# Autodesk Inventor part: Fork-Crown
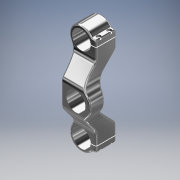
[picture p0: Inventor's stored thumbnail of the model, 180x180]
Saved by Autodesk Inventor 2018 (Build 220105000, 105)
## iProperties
Shininess: 64.0
Length Units: 11272
Angle Units: 11279
Time Units: 11290
Mass Units: 11286
Length Display Precision: 3
Angle Display Precision: 2
Compacted: True
Created: 2001-11
Part Number: Fork-Crown
Document SubType Name: Modeling
Designer: Autodesk, Inc.
Mass: 96.105 g
Surface Area: 286.056 cm^2
Volume: 96.105 cm^3
Density: 1 g/cm^3
Material: Generic
Appearance: Chrome - Polished
Density: 0.0
Volumn: 0.0
Area: 0.0
PropertySet Name: Model Information
Control State: 0
Master: False
Checked Out: False
Author: Autodesk, Inc.
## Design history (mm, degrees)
sketch "Sketch1"
  geometry: L1 (387.107, 198.738)-(394.972, 198.738); L2 (387.081, 199.805)-(394.972, 199.805); L3 (394.972, 205.703)-(394.972, 199.805); L4 (390.064, 208.878)-(391.797, 208.878); L5 (362.993, 135.224)-(362.993, 160.563); L6 (394.972, 198.738)-(394.972, 166.433); L7 (362.993, 135.224)-(406.863, 135.224); L8 (362.993, 135.224)-(362.993, 109.884); L9 (387.081, 70.642)-(394.972, 70.642); L10 (394.972, 64.744)-(394.972, 70.642); L11 (390.064, 61.569)-(391.797, 61.569); L12 (387.107, 71.709)-(394.972, 71.709); L13 (394.972, 71.709)-(394.972, 104.014); A1 r 13.97 centre (373.138, 198.936) between (387.081, 199.805) and (387.107, 198.738); A2 r 3.175 centre (391.797, 205.703) between (394.972, 205.703) and (391.797, 208.878); A3 r 3.048 centre (390.064, 211.926) between (387.646, 210.07) and (390.064, 208.878); A4 r 18.288 centre (373.138, 198.936) between (387.646, 210.07) and (356.426, 191.509); A5 r 76.2 centre (286.793, 160.563) between (362.993, 160.563) and (356.426, 191.509); A6 r 25.4 centre (420.372, 166.433) between (394.972, 166.433) and (401.412, 149.532); A7 r 21.504 centre (385.359, 135.224) between (406.863, 135.224) and (401.412, 149.532); A8 r 76.2 centre (286.793, 109.884) between (356.426, 78.938) and (362.993, 109.884); A9 r 18.288 centre (373.138, 71.511) between (356.426, 78.938) and (387.646, 60.377); A10 r 3.175 centre (391.797, 64.744) between (391.797, 61.569) and (394.972, 64.744); A11 r 3.048 centre (390.064, 58.521) between (390.064, 61.569) and (387.646, 60.377); A12 r 13.97 centre (373.138, 71.511) between (387.107, 71.709) and (387.081, 70.642); A13 r 25.4 centre (420.372, 104.014) between (401.412, 120.915) and (394.972, 104.014); A14 r 21.504 centre (385.359, 135.224) between (401.412, 120.915) and (406.863, 135.224)
  constraints: 28 point on circle, 26 end point, 18 symmetric about line, 14 centre point, 8 tangent, 3 horizontal, 3 vertical, 1 collinear, 1 concentric, 1 horizontal alignment, 1 perpendicular, 15 other
  dimensions: "d1" = 13.97 radius of A1; "d7" = 76.2 radius of A5; "d9" = 18.288 radius of A4; "d92" = 3.175 radius of A2; "d94" = 5.89767 distance from line of A2.centre L2; "d95" = 1.06735 distance between parallel lines of L2 L1; "d99" = 12.2212 horizontal distance of A7.centre A1.centre; "d100" = 25.4 radius of A6; "d101" = 21.50376 radius of A7; "d102" = 3.048 radius of A3; "d103" = 25.33944 distance of L5.start L5.end; "d104" = 43.87007 distance of L5.start L7.end
extrude "ExtrusionBlind1" new body sketch "Sketch1" distance "d16" = 76.2; taper "d17" = 0 deg
node "WorkPlane1"
workaxis "Work Axis4"
sketch "Sketch9"
  geometry: L1 (28.214, 35.429)-(47.471, 16.806); L2 (47.471, 16.806)-(82.009, 16.806); L3 (82.009, 47.286)-(45.305, 47.286); L4 (45.305, 47.286)-(19.099, 67.761); L5 (19.099, 67.761)-(0.009, 67.761); L6 (0.009, 45.941)-(0.009, 67.761); L7 (0.009, -15.24)-(0.009, 91.44) reference; L8 (25.348, 76.2)-(-25.331, 76.2) reference; L9 (82.009, 0)-(82.009, 76.2) reference; L10 (-25.331, 0)-(25.348, 0) reference; L11 (-28.197, 35.429)-(-47.454, 16.806); L12 (-45.288, 47.286)-(-19.081, 67.761); L13 (-19.081, 67.761)-(0.009, 67.761); L14 (0.009, 45.941)-(0.009, 67.761); L15 (-81.992, 47.286)-(-45.288, 47.286); L16 (-47.454, 16.806)-(-81.992, 16.806); L17 (-81.992, 0)-(-81.992, 76.2) reference; A1 r 37.592 centre (2.081, 8.406) between (28.214, 35.429) and (0.009, 45.941); A2 r 37.592 centre (-2.064, 8.406) between (0.009, 45.941) and (-28.197, 35.429)
  constraints: 24 end point, 5 point on line, 5 symmetric about line, 4 point on circle, 3 horizontal, 2 centre point, 1 tangent, 1 vertical, 7 other
  dimensions: "d26" = 30.48 vertical distance of L1.end L3.end; "d30" = 37.592 radius of A1; "d105" = 8.43916 distance between parallel lines of L5 L8; "d106" = 8.40601 distance from line of L10 A1.centre; "d108" = 142 deg angle of L4 L5; "d109" = 19.09001 distance of L4.end L5.end; "d110" = 20.47486 distance between parallel lines of L5 L3; "d111" = 135.959 deg angle of L2 L1
extrude "ExtrusionThru1" sketch "Sketch9" extent not by distance; stored distance "d35" = 3.302; taper "d36" = 0 deg
fillet "Fillet1" dims "d38" = 12.7
fillet "Fillet3" dims "d73" = 6.35
sketch "Sketch15"
  geometry: L1 (6.35, -28.694)-(6.35, -5.08); L2 (6.35, -5.08)-(29.21, -5.08); L3 (0, 16.052)-(0, 0) reference; L4 (35.262, 0)-(0, 0) reference; A1 r 19.05 centre (9.613, -47.462) between (22.86, -33.772) and (6.35, -28.694); A2 r 76.2 centre (99.038, -35.583) between (29.21, -5.08) and (22.86, -33.772); A3 r 21.504 centre (9.613, -47.462) between (-6.439, -33.154) and (-6.439, -61.771) reference; 3 further points
  constraints: 4 end point, 4 point on circle, 2 centre point, 1 coincident, 1 perpendicular, 2 other
  dimensions: "d113" = 6.35 distance between parallel lines of L1 L3; "d114" = 5.08 distance between parallel lines of L4 L2; "d115" = 76.2 radius of A2; "d116" = 22.86 distance of L1.end L2.end; "d117" = 19.05 radius of A1; "d118" = 6.35 horizontal distance of A1.start L2.end
extrude "Extrusion4" cut sketch "Sketch15" distance "d75" = 25.4; taper "d76" = 0 deg
fillet "Fillet5" dims "d77" = 5.08
workplane "Work Plane5"
mirror "Mirror1"
sketch "Sketch16"
  geometry: L1 (-22.366, 14.717)-(15.696, 14.717) reference; L2 (-22.366, 14.717)-(-22.366, -14.717) reference; L3 (15.696, -14.717)-(-22.366, -14.717) reference; A1 r 25.4 centre (35.013, -31.21) between (16.052, -14.309) and (15.696, -14.717) reference; A2 r 21.504 centre (0, 0) between (16.052, -14.309) and (16.052, 14.309) reference; A3 r 25.4 centre (35.013, 31.21) between (15.696, 14.717) and (16.052, 14.309) reference
hole "Hole6" sketch "Sketch16" at (0, 0) diameter "d80" = 28.575; stored, may be unused: countersink angle "d84" = 82 deg, drill point angle "d86" = 118 deg; dims "d81" = 12.7, "d82" = 9.525, "d83" = 6.35, "d85" = 19.05
fillet "Fillet6" dims "d120" = 2.54
workplane "Work Plane6"
sketch "Sketch18"
  geometry: L1 (-21.834, 19.346)-(-21.834, 44.746) reference; 2 further points
  constraints: 1 vertical alignment
  dimensions: "d121" = 15.875 distance of point (-18.659, 24.052) point (-18.659, 39.927); "d129" = 3.175 distance from line of point (-18.659, 39.927) L1
hole "Hole7" sketch "Sketch18" at (-18.659, 39.927), (-18.659, 24.052) diameter "d122" = 3.2512; stored, may be unused: countersink angle "d126" = 82 deg, drill point angle "d128" = 118 deg; dims "d123" = 12.7, "d124" = 6.35, "d125" = 11.43, "d127" = 25.4
mirror "Mirror2"
body "Solid1"
node "Projected Loop1"
other parameters: "mdtd132" = 1.3 [user parameter], "mdtd133" = 3.8 [user parameter], "mdtd136" = 1 [user parameter], "d0" = 14.732 (derived), "d2" = 127 (derived), "d4" = 20.574 (derived), "d6" = 76.2 (derived), "d8" = 18.288 (derived), "d10" = 1.016 (derived), "d12" = 25.4 (derived), "d14" = 23.622 (derived), "d18" = 0, "d19" = 0, "d20" = 0, "d21" = 0, "d22" = 0, "d23" = 0, "d25" = 30.48 (derived), "d27" = 38.354 (derived), "d29" = 37.592 (derived), "d31" = 50.8 (derived), "d33" = 142 deg (derived), "d37" = 0, "d39" = 0, "Hole" = 28.575 [user parameter], "d119" = 0
